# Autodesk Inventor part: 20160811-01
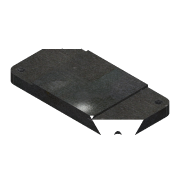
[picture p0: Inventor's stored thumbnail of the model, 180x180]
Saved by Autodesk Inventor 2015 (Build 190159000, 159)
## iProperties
Created: 2016-08
Part Number: 20160811-01
Material: Ocel
Document SubType Name: Modeling
Designer: navara
Density: 7.85 g/cm^3
Appearance: Plech
Beppe: 20160811-01.ipt
Author: navara
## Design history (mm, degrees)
sketch "Náčrt1"
  geometry: L1 (-106.275, 53.278)-(43.725, 53.278); L2 (43.725, 53.278)-(43.725, -21.722); L3 (43.725, -21.722)-(-106.275, -21.722); L4 (-106.275, -21.722)-(-106.275, 53.278); L5 (-106.275, 53.278)-(43.725, -21.722); L6 (43.725, 53.278)-(-106.275, -21.722); 1 further point
  constraints: 12 end point, 2 midpoint, 2 parallel, 1 horizontal, 1 perpendicular
  dimensions: "d0" = 150 distance of L2.end L3.end; "d1" = 75 distance of L1.end L2.end
extrude "Vysunutí1" new body sketch "Náčrt1" distance "d2" = 15; taper "d3" = 0 deg
fillet "Zaoblení1" dims "d4" = 10
sketch "Náčrt2"
  geometry: L1 (-96.275, -21.722)-(33.725, -21.722) reference; L2 (43.725, -11.722)-(43.725, 43.278) reference; L3 (33.725, 53.278)-(-96.275, 53.278) reference; L4 (-106.275, 43.278)-(-106.275, -11.722) reference; A1 r 10 centre (-96.275, -11.722) between (-106.275, -11.722) and (-96.275, -21.722) reference; A2 r 10 centre (33.725, -11.722) between (33.725, -21.722) and (43.725, -11.722) reference; A3 r 10 centre (33.725, 43.278) between (43.725, 43.278) and (33.725, 53.278) reference; A4 r 10 centre (-96.275, 43.278) between (-96.275, 53.278) and (-106.275, 43.278) reference
hole "Díra1" sketch "Náčrt2" at (-96.275, -11.722), (33.725, -11.722), (33.725, 43.278), (-96.275, 43.278) diameter "d5" = 8.376; stored, may be unused: countersink angle "d9" = 90 deg, drill point angle "d11" = 118 deg; dims "d6" = 20, "d7" = 4, "d8" = 2, "d10" = 8
sketch "Náčrt3"
  geometry: L1 (-10, 15)-(25, 15); L2 (25, 15)-(25, 12); L3 (25, 12)-(-10, 12); L4 (-10, 12)-(-10, 15); L5 (105, 15)-(140, 15); L6 (140, 15)-(140, 12); L7 (140, 12)-(105, 12); L8 (105, 12)-(105, 15); L9 (-10, 15)-(-10, 0) reference; L10 (140, 0)-(140, 15) reference; L11 (0, 15)-(130, 15) reference
  constraints: 16 end point, 4 collinear, 4 parallel, 2 horizontal, 2 perpendicular, 2 point on line
  dimensions: "d12" = 3 distance of L3.end L1.start; "d15" = 35 distance of L1.start L1.end
extrude "Vysunutí2" cut sketch "Náčrt3" stored distance "d13" = 10; taper "d14" = 0 deg
node "Těleso1"
node "Promítnutá smyčka1"
